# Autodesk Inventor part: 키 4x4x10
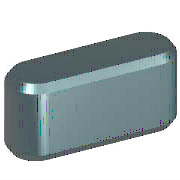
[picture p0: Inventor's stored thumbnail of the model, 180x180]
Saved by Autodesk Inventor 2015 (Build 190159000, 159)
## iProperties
IsCustomPart: 1
Created: 2012-02
Part Number: 키 4x4x10
Material: 강철, 연강
Description: 키 및 해당 키홈
Document SubType Name: Modeling
Standard: KS B 1311
Designer: test
Standards Organization: KS
Language: ko-KR
Size Designation: 4 x 4 x 10
Categories: <MemberInstance><Categories><Category DisplayName="샤프트 부품" InternalName="7f7aeb1f-a693-4053-b835-cee3144e0d98" Mnemonic="SHFT"><Category DisplayName="키" Interna
Density: 1 g/cm^3
Appearance: 노란색
Author: test
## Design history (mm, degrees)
workplane "Work Plane1"
workplane "Work Plane2"
sketch "스케치1"
  geometry: L1 (2, 2)-(8, 2); L2 (8, -2)-(2, -2); L3 (0, 9.4)-(0, -7.4) reference; L4 (-5, 0)-(30, 0) reference; L5 (10, 0)-(10, 7); A1 r 2 centre (2, 0) between (2, 2) and (2, -2); A2 r 2 centre (8, 0) between (8, -2) and (8, 2)
  constraints: 6 end point, 5 point on circle, 4 tangent, 3 point on line, 2 centre point, 1 horizontal, 1 parallel, 1 perpendicular
  dimensions: "d0" = 2 radius of A1 (= 0.5 x PB); "d13" = 2 radius of A2 (= 0.5 x PB); "d14" = 10 distance between parallel lines of L5 L3 (= NLG)
extrude "본체1" new body sketch "스케치1" taper "d3" = 0 deg; stored distance "d4" = 10
workplane "Work Plane3"
body "Solid1"
chamfer "모따기1" distance "d8" = 0.25 (= PHH); stored, may be unused: second distance "d9" = 0.25 (= PHH), angle "d15" = 45 deg
other parameters: "d1" = -2.5 (= -PNT), "d2" = 1.5 (= PH - PNT), "NLG" = 10 [user parameter; used in 3 equation terms], "PB" = 4 [user parameter; used in 2 equation terms], "PNT" = 2.5 [user parameter; used in 2 equation terms], "PH" = 4 [user parameter; used in 1 equation term], "PHH" = 0.25 [user parameter; used in 2 equation terms], "d10" = 0, "d16" = 0, "d17" = 0, "d18" = 0, "WDMAX" = 12 [user parameter], "RR" = 0.08 [user parameter], "PUEB" = 1.8 [user parameter]
